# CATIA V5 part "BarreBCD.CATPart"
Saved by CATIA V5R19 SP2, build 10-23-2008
Part number: BarreBCD
Bounding box of the stored display mesh (mm): x 179.065 to 189.065, y 8 to 93.207, z 138.005 to 183.207
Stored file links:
  D:\France\IFMA\IAO\Projet\BarreBCD.CATPart
  D:\France\IFMA\IAO\Projet\pruangdaja_CAO.CATProduct
  D:\France\IFMA\IAO\Projet\SqueletteAB.CATPart
  D:\France\IFMA\IAO\Projet\SqueletteBCD.CATPart
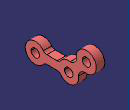
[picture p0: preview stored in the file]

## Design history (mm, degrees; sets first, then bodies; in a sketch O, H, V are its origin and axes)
Body1 (main body)
Body2
  Solid1: linked copy from another document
